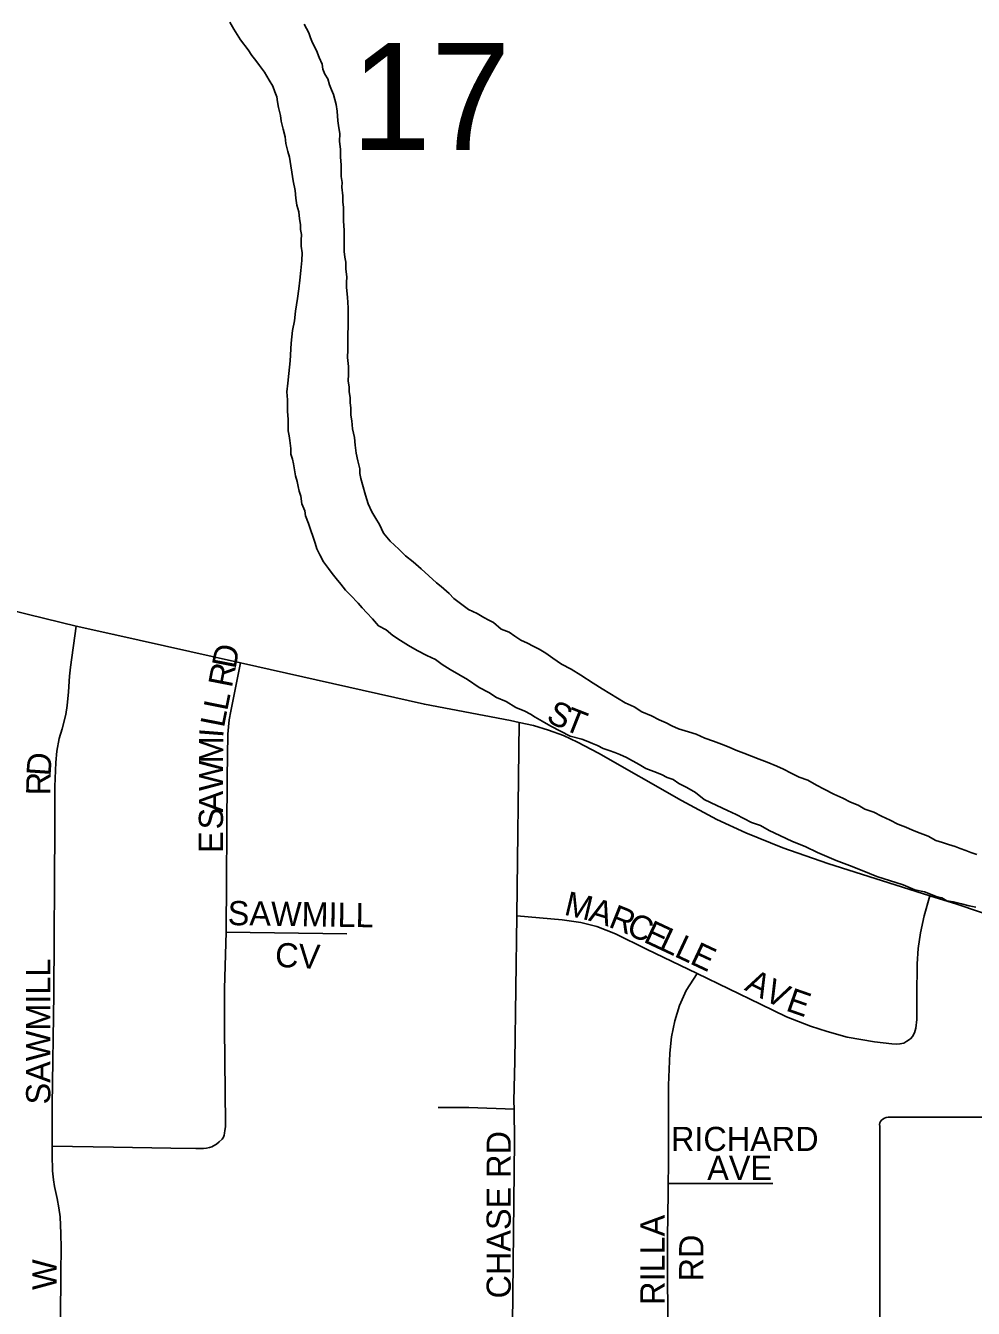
# Model space of a CAD drawing. Extents: x 1587405 to 1714697, y 1028970 to 1155083.
# Drawn here: x 1658024 to 1659980, y 1108229 to 1110877 of the extents above; entities that cross this region are included whole.
import ezdxf

# ---------------------------------------------------------------- set-up
doc = ezdxf.new("R2010")
doc.units = 0
for name, color, linetype in [('GM_X_City_Street', 7, 'Continuous'), ('GM_X_City_Street_Text', 7, 'Continuous'), ('GM_X_Major_River', 7, 'Continuous'), ('GM_X_Section_Text', 7, 'Continuous'), ('GM_X_State_Shield', 7, 'Continuous')]:
    doc.layers.add(name, color=color, linetype=linetype)

msp = doc.modelspace()

# ---------------------------------------------------------------- linework, layer by layer
at = {"layer": 'GM_X_City_Street'}
for points in [[(1657723.2, 1109737.5), (1658030.5, 1109661), (1658129, 1109637.1)], [(1658079.2, 1108564.3), (1658079.4, 1108648.3), (1658082.6, 1108878.5), (1658084.7, 1109223.8), (1658084.5, 1109306.2), (1658086.8, 1109355.8), (1658089, 1109379), (1658093.9, 1109405.1), (1658100.1, 1109425.5), (1658107.3, 1109454.6), (1658110.2, 1109473.8), (1658112.7, 1109501.6), (1658114.7, 1109533.9), (1658116.7, 1109552.7), (1658129, 1109637.1)], [(1658129, 1109637.1), (1658206.5, 1109620.2), (1658467.7, 1109561.5)], [(1658438.1, 1109005.7), (1658440.2, 1109325), (1658442, 1109414.5), (1658443.4, 1109429.5), (1658444.8, 1109444.1), (1658447.9, 1109461.6), (1658467.7, 1109561.5)], [(1658467.7, 1109561.5), (1658847.4, 1109476.2), (1659024.9, 1109442.5), (1659043.3, 1109438.4)], [(1659038.1, 1109039.4), (1659043.3, 1109438.4)], [(1659043.3, 1109438.4), (1659072.7, 1109431.9), (1659103.9, 1109422.7), (1659134.2, 1109411.4), (1659163.7, 1109397.8), (1659207, 1109374.8), (1659378.2, 1109277.2), (1659450.8, 1109238.4), (1659510.6, 1109210.5), (1659587, 1109179.9), (1659680.1, 1109147.3), (1659890.8, 1109080.8)], [(1659410.6, 1108920.7), (1659541.1, 1108857.1), (1659594.6, 1108831.2), (1659644.1, 1108811.4), (1659678.5, 1108800.7), (1659720.2, 1108789.1), (1659776.7, 1108779.5), (1659812.1, 1108775.3), (1659820.8, 1108774.6), (1659828.8, 1108774.9), (1659837, 1108776.9), (1659843.4, 1108780.4), (1659850.4, 1108785.2), (1659855, 1108790.5), (1659859.2, 1108798.1), (1659861.5, 1108807.7), (1659863.8, 1108825.4), (1659864, 1108874.2), (1659864.2, 1108940.1), (1659866.6, 1108972.1), (1659871.3, 1109004.3), (1659878.6, 1109039.7), (1659890.8, 1109080.8)], [(1659890.8, 1109080.8), (1659946.4, 1109063.2), (1660039.6, 1109031.9), (1660085.2, 1109014.1), (1660129.2, 1108993), (1660171.4, 1108968.5), (1660253.8, 1108914.5), (1660364.8, 1108844), (1660435.7, 1108802.3), (1660522.5, 1108755.2), (1660596.5, 1108719.3), (1660606.9, 1108714.9)], [(1659032.4, 1108640.3), (1659032.3, 1108657.4), (1659034.2, 1108739.6), (1659038.1, 1109039.4)], [(1659038.1, 1109039.4), (1659131.7, 1109031.1), (1659170.3, 1109025.6), (1659203.5, 1109017.3), (1659242.1, 1109002.1), (1659305.7, 1108970.4), (1659410.6, 1108920.7)], [(1658423.9, 1108572.9), (1658430.4, 1108578.8), (1658432.7, 1108582.6), (1658433.9, 1108586.4), (1658435, 1108590.6), (1658435.8, 1108596.3), (1658436.6, 1108603.8), (1658437.2, 1108610.7), (1658436.5, 1108676.4), (1658435, 1108807.6), (1658435.2, 1108889.3), (1658438.1, 1109005.7)], [(1658438.1, 1109005.7), (1658687.3, 1109002.1)], [(1659350.9, 1108487.3), (1659351, 1108524.2), (1659351.4, 1108689.8), (1659353.9, 1108756.3), (1659357.4, 1108789.6), (1659364.1, 1108822.5), (1659374.3, 1108854.5), (1659387.4, 1108885.4), (1659410.6, 1108920.7)], [(1658875.7, 1108643.8), (1658939.2, 1108643.8), (1659032.4, 1108640.3)], [(1659028.2, 1108148.9), (1659029.4, 1108196.9), (1659033.1, 1108575.2), (1659032.4, 1108640.3)], [(1658079.2, 1108564.3), (1658205.9, 1108562.2), (1658324.3, 1108560), (1658375.6, 1108558.9), (1658384.5, 1108558.9), (1658391.3, 1108559.3), (1658397.4, 1108560.1), (1658403.9, 1108561.3), (1658408.6, 1108562.9), (1658412.5, 1108564.7), (1658418.1, 1108568.2), (1658423.9, 1108572.9)], [(1658096.3, 1108167.5), (1658096.6, 1108205.4), (1658097.2, 1108304.3), (1658097.5, 1108353.4), (1658096.8, 1108383.9), (1658095.4, 1108418), (1658093.1, 1108436.5), (1658089.3, 1108455.7), (1658086.7, 1108468.4), (1658084.2, 1108481.1), (1658081.8, 1108494.5), (1658080, 1108513.1), (1658079.4, 1108546.4), (1658079.2, 1108564.3)], [(1659349.6, 1108141.1), (1659349.3, 1108375.2), (1659350.8, 1108467.6), (1659350.9, 1108487.3)], [(1659350.9, 1108487.3), (1659378.3, 1108487.3), (1659566.8, 1108487.3)]]:
    msp.add_lwpolyline(points, dxfattribs=at)
at = {"layer": 'GM_X_Major_River'}
for points in [[(1658446, 1110883.8), (1658453.8, 1110869.6), (1658467.7, 1110847.3), (1658483.5, 1110827), (1658491.4, 1110814.8), (1658499.3, 1110804.7), (1658507.3, 1110794.6), (1658517.2, 1110780.4), (1658527, 1110764.1), (1658534.9, 1110752), (1658538.8, 1110739.9), (1658542.7, 1110729.8), (1658544.6, 1110719.7), (1658546.5, 1110707.6), (1658550.3, 1110691.5), (1658552.1, 1110679.4), (1658556, 1110663.3), (1658559.8, 1110647.2), (1658561.6, 1110633.1), (1658565.4, 1110617), (1658569.3, 1110604.9), (1658576.8, 1110556.6), (1658580.5, 1110536.4), (1658582.4, 1110520.3), (1658584.2, 1110506.3), (1658588, 1110492.1), (1658589.9, 1110478.1), (1658591.7, 1110466), (1658591.6, 1110455.9), (1658593.5, 1110445.9), (1658593.3, 1110433.8), (1658593.2, 1110421.8), (1658595, 1110407.7), (1658594.8, 1110391.6), (1658592.6, 1110371.6), (1658590.3, 1110351.5), (1658588, 1110333.4), (1658585.8, 1110313.4), (1658581.4, 1110287.3), (1658579.2, 1110267.3), (1658574.9, 1110247.2), (1658572.5, 1110221.1), (1658570.1, 1110185), (1658567.7, 1110158.9), (1658565.4, 1110138.9), (1658563.2, 1110120.8), (1658565, 1110104.7), (1658564.9, 1110092.7), (1658564.7, 1110080.6), (1658566.5, 1110064.5), (1658566.3, 1110050.4), (1658566.2, 1110040.4), (1658568.1, 1110030.3), (1658570, 1110020.3), (1658571.8, 1110004.2), (1658571.7, 1109992.1), (1658575.5, 1109982), (1658577.4, 1109972), (1658579.3, 1109959.9), (1658581.2, 1109947.8), (1658585, 1109935.7), (1658586.9, 1109925.6), (1658588.8, 1109915.6), (1658592.7, 1109905.5), (1658594.5, 1109889.4), (1658600.4, 1109875.2)], [(1658690.6, 1110157.3), (1658690.8, 1110173.4), (1658689, 1110191.5), (1658689.2, 1110207.6), (1658689.4, 1110221.6), (1658689.6, 1110237.7), (1658689.8, 1110257.8), (1658690, 1110269.8), (1658690.1, 1110279.9), (1658690.3, 1110293.9), (1658688.5, 1110316.1), (1658686.8, 1110336.2), (1658686.9, 1110346.2), (1658687.1, 1110358.3), (1658685.2, 1110374.3), (1658685.4, 1110388.4), (1658683.5, 1110398.5), (1658681.7, 1110410.6), (1658681.9, 1110424.6), (1658682, 1110434.7), (1658682.2, 1110454.8), (1658680.5, 1110472.9), (1658680.7, 1110488.9), (1658680.8, 1110501), (1658678.9, 1110513.1), (1658679.1, 1110525.1), (1658677.3, 1110543.2), (1658677.4, 1110553.2), (1658675.6, 1110565.3), (1658675.8, 1110579.4), (1658675.9, 1110589.4), (1658674.1, 1110605.5), (1658674.3, 1110621.6), (1658672.5, 1110637.7), (1658672.7, 1110653.8), (1658670.8, 1110665.8), (1658669, 1110679.9), (1658667.2, 1110700), (1658665.4, 1110714.1), (1658659.6, 1110734.3), (1658655.7, 1110744.4), (1658651.8, 1110754.5), (1658647.9, 1110766.6), (1658642, 1110776.7), (1658638.1, 1110786.8), (1658636.2, 1110796.9), (1658630.4, 1110811), (1658624.5, 1110825.2), (1658616.6, 1110841.3), (1658612.7, 1110851.4), (1658608.8, 1110861.5), (1658599, 1110879.7)], [(1659987.3, 1109166), (1659975.2, 1109170.1), (1659965.2, 1109174.3), (1659953.2, 1109178.5), (1659943.2, 1109182.6), (1659929.1, 1109186.8), (1659917.1, 1109191), (1659903, 1109195.2), (1659887, 1109203.5), (1659871, 1109209.7), (1659855, 1109215.9), (1659840.9, 1109222.1), (1659824.9, 1109228.4), (1659808.9, 1109236.6), (1659790.9, 1109244.9), (1659774.9, 1109253.1), (1659756.8, 1109259.4), (1659742.8, 1109267.6), (1659726.8, 1109273.9), (1659710.8, 1109282.1), (1659692.7, 1109290.4), (1659672.7, 1109300.7), (1659656.7, 1109308.9), (1659638.7, 1109319.2), (1659620.7, 1109325.5), (1659604.7, 1109333.7), (1659588.7, 1109342), (1659574.6, 1109348.2), (1659554.6, 1109356.5), (1659538.6, 1109362.7), (1659522.5, 1109368.9), (1659506.5, 1109375.2), (1659490.5, 1109381.4), (1659476.4, 1109387.6), (1659460.4, 1109393.9), (1659444.4, 1109400.1), (1659426.3, 1109406.4), (1659408.3, 1109414.6), (1659392.2, 1109418.9), (1659372.2, 1109425.2), (1659358.2, 1109431.4), (1659346.2, 1109437.6), (1659332.1, 1109443.8), (1659316.1, 1109452), (1659296.1, 1109460.3), (1659280.1, 1109470.6), (1659262.1, 1109478.8), (1659214.1, 1109507.6), (1659196.1, 1109519.9), (1659170.1, 1109536.3), (1659150.2, 1109548.6), (1659130.1, 1109558.9), (1659112.2, 1109571.2), (1659098.2, 1109581.4), (1659084.2, 1109589.6), (1659072.2, 1109595.8), (1659060.2, 1109602), (1659046.2, 1109608.2), (1659034.2, 1109616.4), (1659022.2, 1109624.6), (1659006.2, 1109630.8), (1658990.2, 1109645.1), (1658980.2, 1109649.3), (1658970.2, 1109655.4), (1658956.2, 1109663.6), (1658938.2, 1109671.9), (1658922.3, 1109684.2), (1658908.3, 1109694.4), (1658898.3, 1109704.6), (1658882.4, 1109718.9), (1658872.4, 1109727), (1658856.5, 1109741.3), (1658840.6, 1109755.6), (1658824.6, 1109769.8), (1658808.7, 1109782.1), (1658794.8, 1109796.3), (1658776.8, 1109812.6), (1658762.9, 1109828.9), (1658755.1, 1109847.1), (1658747.2, 1109859.2), (1658739.3, 1109873.4), (1658731.5, 1109889.6), (1658725.7, 1109907.8), (1658719.9, 1109929.9), (1658716, 1109942), (1658714.2, 1109952.1), (1658714.3, 1109962.1), (1658710.4, 1109978.3), (1658706.6, 1109994.4), (1658704.8, 1110010.5), (1658703, 1110026.6), (1658699.2, 1110044.7), (1658697.4, 1110060.8), (1658695.5, 1110072.9), (1658695.7, 1110086.9), (1658693.9, 1110099), (1658694, 1110109.1), (1658692.1, 1110121.1), (1658692.2, 1110131.2), (1658690.4, 1110143.2), (1658690.6, 1110157.3)], [(1658600.4, 1109875.2), (1658602.3, 1109865.2), (1658608.1, 1109849), (1658621.7, 1109808.6), (1658625.6, 1109796.6), (1658631.5, 1109784.4), (1658639.3, 1109770.3), (1658649.2, 1109756.1), (1658657.2, 1109745.9), (1658665.1, 1109735.8), (1658675, 1109723.6), (1658684.9, 1109711.4), (1658694.9, 1109701.2), (1658710.8, 1109684.9), (1658718.7, 1109674.8), (1658728.6, 1109664.6), (1658740.6, 1109652.4), (1658752.5, 1109638.2), (1658768.5, 1109629.9), (1658782.4, 1109617.7), (1658798.4, 1109607.4), (1658814.4, 1109597.2), (1658832.4, 1109586.9), (1658852.4, 1109576.6), (1658870.4, 1109568.3), (1658884.4, 1109558.1), (1658900.4, 1109547.8), (1658918.4, 1109537.6), (1658936.4, 1109527.3), (1658960.4, 1109510.9), (1658980.4, 1109500.6), (1658996.3, 1109490.3), (1659016.4, 1109482.1), (1659036.4, 1109469.7), (1659054.4, 1109461.5), (1659066.4, 1109455.3), (1659076.4, 1109449.1), (1659090.4, 1109440.9), (1659108.4, 1109430.6), (1659128.4, 1109420.3), (1659148.4, 1109410), (1659172.5, 1109403.7), (1659184.5, 1109399.5), (1659194.6, 1109395.3), (1659204.6, 1109391.2), (1659216.6, 1109385), (1659228.6, 1109380.8), (1659240.6, 1109376.7), (1659250.7, 1109372.5), (1659264.7, 1109366.3), (1659290.7, 1109351.9), (1659304.7, 1109343.7), (1659320.7, 1109337.4), (1659336.8, 1109331.2), (1659348.8, 1109325), (1659360.8, 1109320.8), (1659372.8, 1109312.6), (1659388.8, 1109304.4), (1659406.8, 1109294.1), (1659424.7, 1109279.8), (1659450.8, 1109267.4), (1659472.8, 1109257.1), (1659490.8, 1109248.8), (1659506.8, 1109240.6), (1659522.8, 1109232.3), (1659540.9, 1109226.1), (1659558.9, 1109215.8), (1659580.9, 1109205.4), (1659606.9, 1109193.1), (1659633, 1109182.7), (1659659, 1109170.3), (1659697.1, 1109153.7), (1659725.1, 1109143.3), (1659751.2, 1109132.9), (1659781.2, 1109120.5), (1659835.4, 1109103.7), (1659859.5, 1109093.3), (1659879.5, 1109089), (1659905.6, 1109078.6), (1659915.6, 1109076.5), (1659925.6, 1109070.4), (1659939.7, 1109068.2), (1659955.8, 1109063.9), (1659971.8, 1109059.7), (1659985.9, 1109057.5)]]:
    msp.add_lwpolyline(points, dxfattribs=at)
at = {"layer": 'GM_X_State_Shield'}
for p, q in [((1660314, 1108623.9), (1659804.4, 1108623.9)), ((1659787.2, 1108605.7), (1659787.2, 1107549.1))]:
    msp.add_line(p, q, dxfattribs=at)
msp.add_ellipse((1659807.2, 1108607.9), major_axis=(20.2, 0), ratio=0.8, start_param=1.712693, end_param=3.28349, dxfattribs=at)

# ---------------------------------------------------------------- texts
at = {"layer": 'GM_X_City_Street_Text'}
for s, rotation, p in [('D', 79.0092, (1658457.5, 1109547.5)), ('R', 78.9906, (1658449.9, 1109508.6)), ('L', 78.5883, (1658440.3, 1109460.8)), ('S', 334.229, (1659096.7, 1109441.6)), ('T', 338.3786, (1659132.1, 1109424.7)), ('L', 78.9473, (1658433.6, 1109426.3)), ('I', 85.5812, (1658432.1, 1109405.9)), ('M', 89.9089, (1658432.1, 1109354.1)), ('D', 86.0405, (1658075.8, 1109326.8)), ('W', 89.9117, (1658432, 1109296.9)), ('R', 89.2957, (1658075.4, 1109287.9)), ('A', 89.8907, (1658431.9, 1109252.9)), ('S', 89.9073, (1658431.8, 1109217.7)), ('E', 89.918, (1658431.8, 1109169.3)), ('SAWMILL', 359.1191, (1658441.3, 1109020.3)), ('M', 346.5999, (1659133.8, 1109042.1)), ('A', 342.8989, (1659184.4, 1109030.1)), ('R', 338.0994, (1659225.4, 1109017.5)), ('C', 335.3249, (1659261.5, 1109003)), ('E', 334.9138, (1659297.4, 1108986.5)), ('L', 334.889, (1659329.3, 1108971.6)), ('L', 334.9175, (1659361.2, 1108956.7)), ('CV', 356.989, (1658538.3, 1108934.4)), ('E', 334.9175, (1659393.1, 1108941.7)), ('SAWMILL', 90, (1658075.4, 1108650.1)), ('A', 333.1221, (1659506.1, 1108887.1)), ('V', 333.1026, (1659545.3, 1108867.3)), ('E', 340.809, (1659591.3, 1108844.5)), ('CHASE RD', 90, (1659025.8, 1108249.7)), ('RICHARD', 0, (1659356.4, 1108553.9)), ('AVE', 0, (1659431.2, 1108494.3)), ('RILLA', 90, (1659343.2, 1108236.5)), ('RD', 90, (1659423.2, 1108284.9)), ('W', 90, (1658088.6, 1108267.3))]:
    msp.add_text(s, height=50, rotation=rotation, dxfattribs=at).set_placement(p)
at = {"layer": 'GM_X_Section_Text'}
msp.add_text('17', height=221, rotation=0, dxfattribs=at).set_placement((1658696.4, 1110620))

doc.saveas('drawing.dxf')
